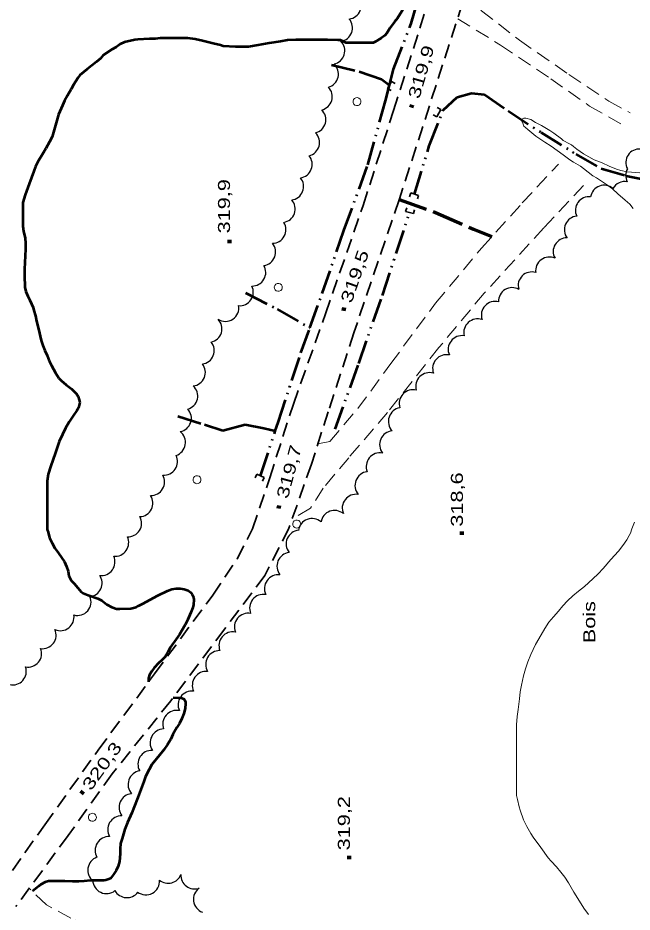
# Model space of a CAD drawing. Extents: x 240591 to 242335, y 5323482 to 5326937.
# Drawn here: x 241636.3 to 241789.5, y 5325422 to 5325645.2 of the extents above; entities that cross this region are included whole.
import ezdxf

# ---------------------------------------------------------------- set-up
doc = ezdxf.new("R2010")
doc.units = 0
doc.header["$LTSCALE"] = 1.2
for name, pattern in [('DASH_DOUBLE_DOT', [9.2, 5, -1.2, 0.3, -1.2, 0.3, -1.2]), ('LONG_DASHED', [7.5, 6, -1.5]), ('MEDIUM_DASHED', [4.5, 3, -1.5])]:
    doc.linetypes.add(name, pattern=pattern)
for name, color, linetype, lineweight in [('1', 7, 'Continuous', 53), ('19', 7, 'Continuous', 13), ('2', 7, 'Continuous', 13), ('21', 7, 'Continuous', 53), ('22', 7, 'LONG_DASHED', 70), ('26', 7, 'Continuous', 35), ('3', 7, 'Continuous', 140), ('36', 7, 'Continuous', 13), ('4', 7, 'DASH_DOUBLE_DOT', 53), ('44', 7, 'Continuous', 25)]:
    doc.layers.add(name, color=color, linetype=linetype, lineweight=lineweight)

msp = doc.modelspace()

# ---------------------------------------------------------------- linework, layer by layer
at = {"layer": '1'}
for points in [[(241736.8, 5325658.9), (241736.6, 5325655.9), (241736.3, 5325654.6), (241735.6, 5325653.4), (241734.6, 5325651.2), (241733.6, 5325649.3), (241732.8, 5325648.1), (241732.1, 5325646.9), (241731, 5325645.1), (241730.2, 5325644.2), (241729.1, 5325642.6), (241728.3, 5325641.4), (241727.8, 5325640.8), (241726.9, 5325640.1), (241725.4, 5325639.2), (241724.9, 5325639), (241724.3, 5325639), (241723, 5325639), (241720, 5325639), (241718.2, 5325639), (241717.7, 5325639.2), (241716.8, 5325639.6), (241716.2, 5325639.6), (241716.1, 5325639.6)], [(241653.8, 5325501.1), (241656.2, 5325500.3), (241657.2, 5325499.8), (241658.5, 5325498.8), (241659.7, 5325498.1), (241660.9, 5325497.7), (241661.7, 5325497.7), (241664.5, 5325497.8), (241665.8, 5325498.1), (241666.4, 5325498.4), (241667.5, 5325499), (241669.2, 5325499.9), (241671.2, 5325501), (241673.6, 5325502.2), (241674.7, 5325502.6), (241675.8, 5325502.8), (241676.8, 5325502.8), (241677.8, 5325502.6), (241678.8, 5325502.3), (241679.4, 5325501.8), (241679.8, 5325501.3), (241680.1, 5325500.6), (241680.2, 5325500), (241680.1, 5325498.7), (241679.9, 5325498), (241679.4, 5325496.8), (241678.7, 5325495), (241678, 5325493.7), (241676.6, 5325491.3), (241675.8, 5325490.1), (241674.3, 5325488), (241673.7, 5325486.8), (241673, 5325485.7), (241672.2, 5325484.9), (241671.4, 5325484.1), (241670.3, 5325483), (241669.7, 5325482.1), (241669.1, 5325481.2), (241668.9, 5325480.4), (241668.9, 5325479.5)], [(241675, 5325475.6), (241677, 5325475.5), (241677.7, 5325475.2), (241678.1, 5325474.6), (241678.1, 5325474.1), (241678, 5325472.8), (241677.7, 5325471.6), (241677.2, 5325470.3), (241676.6, 5325469.1), (241675.9, 5325468.1), (241674.9, 5325466.3), (241674.4, 5325465.2), (241673.6, 5325463.8), (241672.7, 5325462.5), (241671.6, 5325461.2), (241669.7, 5325458.8), (241669, 5325457.6), (241668.1, 5325455.8), (241667.7, 5325454.6), (241667.2, 5325453.3), (241666.2, 5325450.6), (241665.3, 5325448.3), (241664.7, 5325446.8), (241663.6, 5325444.4), (241663, 5325442.7), (241662.3, 5325440.4), (241661.9, 5325439.1), (241661.8, 5325437.8), (241661.8, 5325436.5), (241661.6, 5325434.6), (241661.3, 5325433.5), (241660.8, 5325432.4), (241660.1, 5325431.4), (241659.4, 5325430.4), (241658.7, 5325430.1), (241658.2, 5325430), (241657.7, 5325429.9), (241656, 5325429.9), (241654.4, 5325429.9), (241652.8, 5325429.7), (241651.5, 5325429.6), (241649.9, 5325429.6), (241648, 5325429.7), (241646.4, 5325429.7), (241643.9, 5325429.7), (241643.1, 5325429.5), (241642, 5325428.9), (241641.5, 5325428.5), (241639.9, 5325427.2)]]:
    msp.add_lwpolyline(points, dxfattribs=at)
at = {"layer": '1', "linetype": 'LONG_DASHED'}
for points in [[(241716.1, 5325639.6), (241713.5, 5325639.7), (241711.2, 5325639.7), (241708.6, 5325639.7), (241705.6, 5325639.7), (241703.5, 5325639.6), (241701.8, 5325639.3), (241699, 5325638.9), (241696.2, 5325638.4), (241693.8, 5325638), (241692.5, 5325638), (241690.6, 5325638), (241687.5, 5325638.1), (241686.8, 5325638.4), (241685, 5325638.8), (241682.3, 5325639.5), (241680.5, 5325639.9), (241678.7, 5325640.1), (241677.1, 5325640.1), (241674.3, 5325640.1), (241671.8, 5325640.1), (241670.5, 5325640), (241669.1, 5325640), (241666.2, 5325639.8), (241665.5, 5325639.7), (241662.9, 5325639.1), (241661.8, 5325638.6), (241660.8, 5325637.9), (241659.7, 5325637.3), (241657.6, 5325635.9), (241656.9, 5325635.1), (241655.9, 5325634.2), (241654.7, 5325633.3), (241653.6, 5325632.4), (241651.7, 5325630.9), (241651.3, 5325630.3), (241650.2, 5325628.5), (241649.6, 5325627.4), (241648.7, 5325625.8), (241647.9, 5325624.5), (241647.4, 5325623.3), (241646.4, 5325621.1), (241646, 5325619.6), (241645.2, 5325616.7), (241644.8, 5325615.5), (241644.2, 5325614.3), (241643.3, 5325612.6), (241642.7, 5325611.6), (241641.3, 5325609.3), (241640.7, 5325608.1), (241640.3, 5325606.9), (241639.1, 5325603.8), (241638.1, 5325601), (241637.5, 5325599.1), (241637.5, 5325598.6), (241637.5, 5325597.4), (241637.5, 5325594.4), (241637.5, 5325593.2), (241637.7, 5325592), (241638.1, 5325590.2), (241638.2, 5325589), (241638.2, 5325587.6), (241638.1, 5325585.6), (241638, 5325584.3), (241637.9, 5325582.3), (241637.9, 5325580.9), (241638, 5325578), (241638.3, 5325576.9), (241638.8, 5325575.7), (241639.3, 5325574.7), (241640.1, 5325572.9), (241640.3, 5325572.2), (241640.7, 5325570.8), (241640.9, 5325569.5), (241641.4, 5325567.6), (241642.1, 5325564.7), (241642.5, 5325563.4), (241643, 5325562.2), (241643.6, 5325560.9), (241644.1, 5325559.6), (241644.7, 5325558.4), (241645.7, 5325556.6), (241646.5, 5325555.3), (241647.1, 5325554.7), (241648.3, 5325553.6), (241649.7, 5325552.6), (241650.9, 5325551.4), (241651.3, 5325550.7), (241651.6, 5325549.9), (241651.7, 5325549.2), (241651.6, 5325548.5), (241651.4, 5325547.9), (241651, 5325547.2), (241650.1, 5325545.9), (241649.1, 5325544.4), (241648.2, 5325542.8), (241647.4, 5325541.2), (241646.6, 5325539.5), (241646.1, 5325538), (241645.6, 5325536.5), (241644.5, 5325533.4)], [(241644.5, 5325533.4), (241643.8, 5325531.3), (241643.6, 5325529.6), (241643.6, 5325528.7), (241643.6, 5325525.5), (241643.6, 5325522.5), (241643.6, 5325519.5), (241643.6, 5325517.5), (241643.8, 5325516.8), (241644.2, 5325515.4), (241644.8, 5325514.1), (241645.5, 5325512.8), (241646.4, 5325511.6), (241647.9, 5325509.4), (241648.4, 5325508.3), (241648.8, 5325507.1), (241649, 5325505.9), (241649.6, 5325504.8), (241650.3, 5325504), (241651.2, 5325502.9), (241652.1, 5325501.9), (241652.6, 5325501.6), (241653.8, 5325501.1)]]:
    msp.add_lwpolyline(points, dxfattribs=at)
at = {"layer": '19', "linetype": 'MEDIUM_DASHED'}
for points in [[(241748.5, 5325652.6), (241751.9, 5325647), (241761.4, 5325639.6), (241773.7, 5325631.1), (241783.7, 5325624.4), (241789, 5325621.5)], [(241746, 5325645), (241756.7, 5325638.4), (241769.2, 5325630), (241778.9, 5325623.2), (241787, 5325618.6)], [(241711.1, 5325538.9), (241714.1, 5325539.5), (241721.1, 5325547.7), (241729.3, 5325558.9), (241740.5, 5325574), (241751.9, 5325587.7), (241762.1, 5325599), (241771.1, 5325608.7)], [(241777.4, 5325603.4), (241767.5, 5325592.8), (241752.6, 5325576.5), (241741.3, 5325562.9), (241728.5, 5325546.7), (241718.8, 5325535.4), (241712.4, 5325527.8), (241709.3, 5325522.8), (241704.7, 5325520.2)], [(241658.9, 5325416.3), (241649.5, 5325420.5), (241643.4, 5325423.8), (241639.1, 5325427.9)]]:
    msp.add_lwpolyline(points, dxfattribs=at)
at = {"layer": '2'}
for points in [[(241791.4, 5325606.5), (241788.3, 5325606.8), (241786.7, 5325607.1), (241785.6, 5325607.4), (241783.8, 5325608.2), (241782, 5325609), (241780, 5325609.8), (241778.7, 5325610.5), (241777.4, 5325611.3), (241775.7, 5325612.4), (241774.9, 5325613.1), (241774.4, 5325613.5), (241773.9, 5325613.8), (241772.3, 5325614.6), (241771.9, 5325615), (241770, 5325616.4), (241769, 5325617.1), (241766.9, 5325618.3), (241765.4, 5325619.1), (241764.2, 5325619.8), (241763, 5325620.2), (241762.5, 5325620.2), (241762, 5325619.9)], [(241762, 5325619.9), (241762, 5325619.4), (241762.3, 5325618.7), (241762.5, 5325618.2), (241762.9, 5325617.8), (241763.5, 5325617.3), (241765.5, 5325615.7), (241767.7, 5325614.2), (241769.3, 5325613.2), (241770.8, 5325612.1), (241772.3, 5325611), (241774, 5325609.8), (241774.9, 5325609.2), (241776.6, 5325608.2), (241777.4, 5325607.6), (241779.7, 5325605.8), (241780.6, 5325605.3), (241783.1, 5325603.6), (241784.6, 5325602.5), (241785.9, 5325601.3), (241787.8, 5325599.7), (241788.9, 5325598.7), (241789.8, 5325597.6)]]:
    msp.add_lwpolyline(points, dxfattribs=at)
at = {"layer": '2', "linetype": 'LONG_DASHED'}
msp.add_lwpolyline([(241790.1, 5325519.3), (241789.4, 5325517.7), (241789.1, 5325516.6), (241788.8, 5325516), (241788.2, 5325514.9), (241787.2, 5325513.5), (241786.1, 5325512.1), (241784.2, 5325510), (241782.3, 5325507.8), (241781, 5325506.4), (241779.7, 5325505.2), (241777.6, 5325503.3), (241776.1, 5325502.1), (241774.7, 5325500.9), (241773.4, 5325499.7), (241772.2, 5325498.4), (241771.1, 5325497.1), (241769.9, 5325495.7), (241768.7, 5325494.4), (241767.7, 5325492.8), (241766.8, 5325491.2), (241765.4, 5325488.8), (241764.2, 5325486.3), (241763.5, 5325484.5), (241762.9, 5325482.7), (241762.4, 5325481), (241761.9, 5325478.6), (241761.6, 5325477), (241761.4, 5325475.2), (241761.1, 5325472.6), (241760.8, 5325470.8), (241760.7, 5325468.7), (241760.7, 5325467.6), (241760.7, 5325464.6), (241760.7, 5325462), (241760.7, 5325458.8), (241760.7, 5325456.3), (241760.7, 5325453.3), (241760.7, 5325451.1), (241760.9, 5325450.1), (241761.3, 5325448.3), (241761.6, 5325447.4), (241762.4, 5325445), (241763.2, 5325443.4), (241764.2, 5325441.6), (241764.8, 5325440.7), (241766.7, 5325438.1), (241768.6, 5325435.5), (241769.3, 5325434.7), (241770.6, 5325433.3), (241771.7, 5325432), (241772.7, 5325430.7), (241773.6, 5325429.3), (241775, 5325427), (241776, 5325425.4), (241777.5, 5325423), (241778.6, 5325421.4)], dxfattribs=at)
at = {"layer": '21', "linetype": 'MEDIUM_DASHED', "lineweight": 35}
for points in [[(241748.9, 5325654), (241740.6, 5325628.4), (241731.4, 5325599.8), (241720.1, 5325566.6), (241713.7, 5325546.9), (241709.5, 5325533.8), (241703.9, 5325517.8), (241697.9, 5325506), (241687.8, 5325492.6), (241674.4, 5325474.7), (241659.8, 5325456.5), (241648.8, 5325441.1), (241635.8, 5325423.4)], [(241631.8, 5325428), (241643, 5325443.8), (241656.3, 5325462.4), (241670.4, 5325481.5), (241684.9, 5325501.1), (241691, 5325510.2), (241694.8, 5325517.7), (241699.1, 5325530.4), (241705, 5325548.8), (241713, 5325571.3), (241722.4, 5325598.4), (241730, 5325622.1), (241738.5, 5325648.7)]]:
    msp.add_lwpolyline(points, dxfattribs=at)
at = {"layer": '22'}
msp.add_lwpolyline([(241731.4, 5325599.9), (241740.5, 5325596.6), (241749.9, 5325592.5), (241754.5, 5325590.6)], dxfattribs=at)
at = {"layer": '26'}
for p, q in [((241728.5, 5325627.6), (241729.5, 5325629.3)), ((241729.5, 5325629.3), (241730.4, 5325628.8)), ((241728.5, 5325627.6), (241729.4, 5325627.1)), ((241741.8, 5325622.3), (241740.8, 5325620.5)), ((241741.8, 5325622.3), (241740.9, 5325622.8)), ((241740.8, 5325620.5), (241739.9, 5325621)), ((241734.3, 5325601.5), (241734, 5325600.5)), ((241734.3, 5325601.5), (241736.2, 5325600.9)), ((241736.2, 5325600.9), (241736, 5325600)), ((241733, 5325596.9), (241733.3, 5325597.8)), ((241735, 5325596.4), (241735.2, 5325597.3)), ((241735, 5325596.4), (241733, 5325596.9)), ((241695.9, 5325531.3), (241695.5, 5325530.4)), ((241695.9, 5325531.3), (241697.7, 5325530.5)), ((241697.7, 5325530.5), (241697.3, 5325529.6))]:
    msp.add_line(p, q, dxfattribs=at)
at = {"layer": '3'}
for p, q in [((241734.4, 5325622.8), (241734.6, 5325623.5)), ((241689.1, 5325589), (241689.1, 5325589.8)), ((241717.5, 5325572.1), (241717.7, 5325572.9)), ((241701.3, 5325522.7), (241701.5, 5325523.5)), ((241747, 5325516.2), (241747, 5325517)), ((241652.1, 5325451.5), (241652.6, 5325452.2)), ((241718.9, 5325435.2), (241718.9, 5325436))]:
    msp.add_line(p, q, dxfattribs=at)
at = {"layer": '36'}
for centre in [(241720.873, 5325624.3), (241701.223, 5325577.94), (241680.973, 5325529.92), (241705.843, 5325518.84), (241654.883, 5325445.66)]:
    msp.add_ellipse(centre, major_axis=(0.261, -0.965), ratio=0.99964, dxfattribs=at)
at = {"layer": '4'}
msp.add_line((241696.8, 5325530.9), (241700.5, 5325542.1), dxfattribs=at)
for points in [[(241729, 5325628.4), (241730, 5325632.4), (241734.4, 5325643.8), (241736.4, 5325650.8)], [(241714.5, 5325633.5), (241721.4, 5325631.8), (241727, 5325629.9), (241729, 5325628.4)], [(241735.2, 5325601.2), (241738.9, 5325613.3), (241742.4, 5325622.2), (241745.9, 5325625.4), (241749.4, 5325626.4), (241752.7, 5325626.1), (241758.6, 5325622), (241766.8, 5325616.6), (241775.5, 5325611.2), (241781.8, 5325607.6), (241788, 5325605.8), (241796.9, 5325604), (241804.1, 5325600.9), (241811.4, 5325597.1), (241817.7, 5325593.2), (241821.7, 5325593), (241826, 5325596.2), (241830.3, 5325603.6), (241835.4, 5325610.8), (241844, 5325618.8), (241852.3, 5325625.2), (241861.9, 5325630.6), (241867, 5325634.7)], [(241709.1, 5325567.8), (241712.2, 5325576.4), (241717.6, 5325592.1), (241723.6, 5325608.5), (241728, 5325624.5), (241729, 5325628.4)], [(241715.4, 5325542.5), (241721.3, 5325558.9), (241727.2, 5325575.9), (241734, 5325596.6)], [(241693.1, 5325576.6), (241701, 5325572.5), (241709.1, 5325567.8)], [(241700.5, 5325542.1), (241701.2, 5325544.2), (241706.9, 5325561.6), (241709.1, 5325567.8)], [(241676.2, 5325545.8), (241682.8, 5325543.7), (241687.4, 5325542.2), (241693, 5325543.7), (241697.6, 5325542.8), (241700.5, 5325542.1)]]:
    msp.add_lwpolyline(points, dxfattribs=at)
at = {"layer": '44'}
for centre, radius, start, end in [((241699.758, 5325592.336), 3.397, 270.36702, 32.27347), ((241697.176, 5325586.756), 3.399, 278.01722, 39.99079), ((241694.731, 5325581.661), 3.393, 268.63342, 30.63131), ((241755.366, 5325570.961), 3.478, 76.29189, 198.10818), ((241743.191, 5325557.69), 3.446, 77.95947, 199.84762), ((241701.257, 5325502.744), 3.47, 83.32599, 205.31333), ((241697.541, 5325497.856), 3.453, 80.34376, 202.03991), ((241634.998, 5325482.083), 3.388, 257.07787, 19.07704)]:
    msp.add_arc(centre, radius, start, end, dxfattribs=at)
for centre, major_axis, ratio, start_param, end_param in [((241718.507, 5325648.288), (3.153, -1.269), 0.998886, 5.2225084, 7.3449948), ((241716.375, 5325642.709), (3.175, -1.181), 0.999858, 5.2182073, 7.3507075), ((241714.432, 5325637.008), (3.249, -0.985), 0.999994, 5.2199132, 7.3431416), ((241712.853, 5325631.192), (-0.984, 3.247), 0.999994, 3.1148555, 5.2453802), ((241711.328, 5325625.548), (3.253, -0.954), 0.999994, 5.2184374, 7.3435875), ((241709.703, 5325619.797), (3.287, -0.878), 0.999909, 5.2218585, 7.3454674), ((241708.14, 5325614.101), (3.216, -1.096), 0.998629, 5.2751873, 7.3973197), ((241706.317, 5325608.633), (2.781, -1.947), 0.999926, 5.4599047, 7.5862757), ((241791.285, 5325609.103), (0.411, -3.323), 0.999879, 2.9232682, 5.0783309), ((241791.238, 5325605.871), (1.777, -2.838), 0.999984, 3.6345593, 4.6419218), ((241704.164, 5325603.112), (3.155, -1.243), 0.999949, 5.2194052, 7.34823), ((241787.664, 5325601.025), (-1.63, -2.923), 0.999002, 3.4581311, 4.7271957), ((241782.509, 5325600.044), (-0.761, 3.301), 0.999756, 5.3453373, 7.4776728), ((241702.067, 5325597.499), (2.671, -2.097), 0.999961, 5.5445084, 7.6733406), ((241778.77, 5325597.166), (-2.435, 2.383), 0.999825, 5.371946, 7.499402), ((241775.995, 5325592.33), (-3.106, 1.369), 0.999994, 5.2174324, 7.3466547), ((241773.199, 5325586.897), (-2.907, 1.736), 0.999428, 5.2236479, 7.3468929), ((241768.855, 5325582.07), (-2.042, 2.762), 0.99995, 5.2218442, 7.3487891), ((241764.441, 5325578.427), (-2.395, -2.341), 0.999425, 3.632372, 5.7924059), ((241691.617, 5325576.751), (2.827, -1.885), 0.997716, 5.2205118, 7.3364907), ((241759.54, 5325574.518), (-2.867, -1.743), 0.999422, 3.6349663, 5.7898117), ((241688.035, 5325572.798), (2.651, 2.072), 0.999219, 3.4815993, 5.7902233), ((241683.83, 5325567.592), (0.972, 3.229), 0.998974, 3.6376417, 5.7840726), ((241750.946, 5325566.621), (-2.306, 2.559), 0.999647, 5.2202699, 7.3465699), ((241747.078, 5325562.435), (-2.737, 2.106), 0.999978, 5.2192812, 7.3486432), ((241681.904, 5325562.159), (-2.104, 2.627), 0.999983, 2.5931672, 4.7225805), ((241679.659, 5325556.711), (3.139, -1.316), 0.999949, 5.2244739, 7.3486319), ((241738.988, 5325553.211), (-2.429, 2.449), 0.998922, 5.2185379, 7.3464128), ((241677.761, 5325550.827), (3.299, -0.786), 0.999909, 5.2176044, 7.347001), ((241734.83, 5325548.942), (-2.331, 2.535), 0.999265, 5.2926542, 7.4183561), ((241676.174, 5325545.265), (-0.709, 3.316), 0.999994, 3.1138872, 5.2453489), ((241732.198, 5325544.468), (-3.319, 1.087), 0.999979, 5.2153702, 7.3445968), ((241674.631, 5325539.24), (3.399, -0.591), 0.999863, 5.2179216, 7.3497689), ((241729.955, 5325538.675), (-3.048, 1.599), 0.999266, 5.2897939, 7.4179022), ((241672.727, 5325534.453), (2.286, -2.511), 0.999926, 5.4568784, 7.5819131), ((241726.634, 5325533.182), (-2.7, 2.18), 0.99539, 5.2191922, 7.3347978), ((241669.497, 5325529.375), (2.902, -1.747), 0.999994, 5.2197882, 7.3489518), ((241723.863, 5325528.461), (-3.058, 1.701), 0.99977, 5.3498545, 7.4788468), ((241666.573, 5325524.088), (3.027, -1.528), 0.999909, 5.2203559, 7.3461697), ((241720.651, 5325522.815), (-2.74, 2.116), 0.999951, 5.2225406, 7.3461963), ((241715.263, 5325518.859), (-0.393, 3.381), 0.999926, 5.4621098, 7.5845247), ((241663.75, 5325519.053), (2.881, -1.781), 0.999977, 5.2187354, 7.3446936), ((241709.657, 5325516.802), (-1.143, 3.232), 0.995827, 5.225287, 7.3736676), ((241706.607, 5325513.901), (-1.337, -3.139), 0.999755, 3.6314863, 5.7932917), ((241660.537, 5325514.193), (0.276, 3.38), 0.999994, 3.1175986, 5.2444816), ((241657.108, 5325509.385), (1.956, -2.77), 0.99996, 5.5448135, 7.6763509), ((241704.357, 5325508.337), (0.483, -3.413), 0.999995, 3.1193887, 5.2438885), ((241653.921, 5325504.099), (1.523, 3.007), 0.998974, 3.7082544, 5.7874163), ((241651.165, 5325499.406), (0.157, 3.366), 0.998271, 2.916157, 5.1680753), ((241693.738, 5325493.162), (-2.681, 2.174), 0.999648, 5.2182532, 7.3421774), ((241646.885, 5325495.652), (2.088, -2.7), 0.99991, 5.2165414, 7.3450337), ((241642.429, 5325491.141), (-1.353, 3.113), 0.999983, 2.5929375, 4.7205245), ((241689.89, 5325488.503), (-2.652, 2.204), 0.999553, 5.218633, 7.3422915), ((241638.803, 5325486.531), (0.523, 3.354), 0.999994, 3.1175314, 5.2438723), ((241686.594, 5325483.813), (-2.983, 1.749), 0.999978, 5.2206619, 7.3487297), ((241683.244, 5325478.615), (1.456, -3.133), 0.999984, 2.5975306, 4.7185784), ((241679.687, 5325473.723), (-0.345, -3.427), 0.999995, 3.1158691, 5.2449526), ((241675.874, 5325468.902), (-2.341, 2.531), 0.999686, 5.336181, 7.4607825), ((241672.741, 5325464.24), (-3.006, 1.745), 0.998133, 5.2665831, 7.3860017), ((241669.671, 5325458.916), (-2.935, 1.798), 0.998403, 5.2151017, 7.3428513), ((241667.224, 5325453.826), (-3.101, 1.534), 0.999689, 5.3324634, 7.4608739), ((241664.965, 5325448.124), (-3.167, 1.35), 0.99995, 5.2157745, 7.343838), ((241662.147, 5325442.575), (-2.969, 1.752), 0.999553, 5.218391, 7.3442767), ((241659.028, 5325437.373), (-2.816, 2.03), 0.999276, 5.2955985, 7.4178192), ((241657.15, 5325432.451), (-0.523, -3.387), 0.999752, 3.6372775, 5.7875004), ((241658.373, 5325430.032), (-1.098, -3.237), 0.998177, 5.0688167, 7.2865085), ((241668.206, 5325429.724), (1.959, -2.808), 0.999502, 5.027078, 7.314149), ((241673.775, 5325432.616), (1.895, -2.848), 0.99993, 5.0143634, 6.8976767), ((241680.383, 5325431.196), (-1.947, -2.823), 0.999886, 5.2616359, 7.215449), ((241683.495, 5325425.188), (-3.289, -0.923), 0.998974, 5.0664099, 7.2232034), ((241663.491, 5325429.019), (0.199, -3.41), 0.999198, 5.159521, 7.1435714)]:
    msp.add_ellipse(centre, major_axis=major_axis, ratio=ratio, start_param=start_param, end_param=end_param, dxfattribs=at)

# ---------------------------------------------------------------- texts
at = {"layer": '3', "width": 1.35}
for s, height, rotation, p in [('319,9', 2.999, 73.645, (241736.4, 5325624.8)), ('319,9', 3, 90, (241689.2, 5325591.4)), ('319,5', 2.999, 70.878, (241719.5, 5325573.8)), ('319,7', 2.999, 74.908, (241703.6, 5325525)), ('318,6', 3, 90, (241747.3, 5325518.2)), ('320,3', 2.999, 54.15, (241654.5, 5325452.1)), ('319,2', 3, 90, (241719.1, 5325437.4))]:
    msp.add_text(s, height=height, rotation=rotation, dxfattribs=at).set_placement(p)
at = {"layer": '44', "width": 1.35}
msp.add_text('Bois', height=3, rotation=90, dxfattribs=at).set_placement((241780.3, 5325489.1))

doc.saveas('drawing.dxf')
